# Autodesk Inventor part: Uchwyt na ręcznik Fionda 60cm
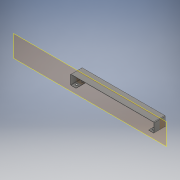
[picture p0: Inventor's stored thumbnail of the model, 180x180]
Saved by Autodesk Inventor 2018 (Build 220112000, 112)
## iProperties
Created: 2020-02
Part Number: Uchwyt na ręcznik Fionda 60cm
Material: Ogólny
Document SubType Name: Modeling
Designer: Marcel
Density: 1 g/cm^3
Appearance: Domyślna
Author: Marcel
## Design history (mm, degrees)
derived "Uchwyt na ręcznik Fionda M.iam"
node "Bryła1"
node "Uchwyt na ręczniki 60 cm.ipt:1"
node "Płaszczyzna konstrukcyjna1"
node "Kapselek.ipt:1"
node "Kapselek.ipt:2"
node "Kapselek.ipt:3"
node "Kapselek.ipt:4"
